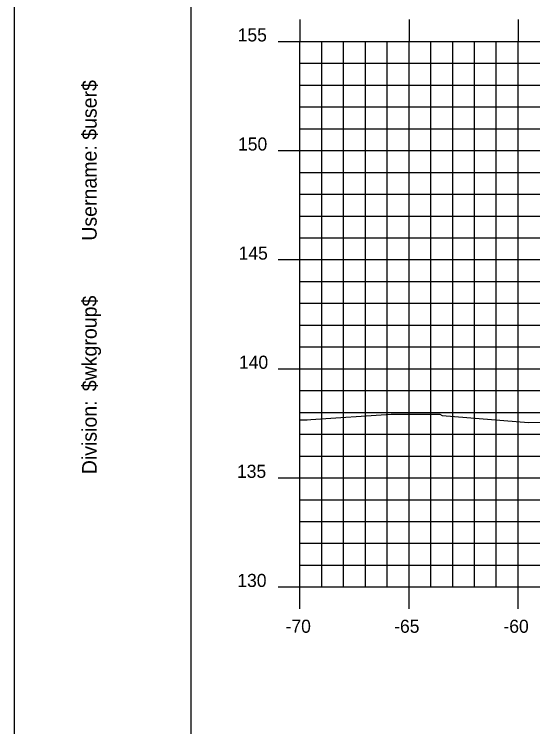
# Model space of a CAD drawing. Extents: x 851639 to 851810, y 365876 to 365986.
# Drawn here: x 851638.56 to 851662.32, y 365908.43 to 365941.08 of the extents above; entities that cross this region are included whole.
import ezdxf

# ---------------------------------------------------------------- set-up
doc = ezdxf.new("R2010")
doc.units = 0
for name, color, linetype in [('BORDER', 7, 'Continuous'), ('H_V ANNOTATION', 7, 'Continuous'), ('MAJOR', 7, 'Continuous'), ('MINOR', 7, 'Continuous'), ('PLOT BOUNDARY', 7, 'Continuous'), ('S_Roadway_Centerline', 7, 'Continuous')]:
    doc.layers.add(name, color=color, linetype=linetype)

msp = doc.modelspace()

# ---------------------------------------------------------------- linework, layer by layer
at = {"layer": 'BORDER'}
msp.add_lwpolyline([(851646.655, 365878.833), (851806.655, 365878.833), (851806.655, 365983.833), (851646.655, 365983.833)], close=True, dxfattribs=at)
at = {"layer": 'MAJOR'}
for p, q in [((851651.655, 365940.835), (851651.655, 365939.833)), ((851656.655, 365940.835), (851656.655, 365939.833)), ((851661.655, 365940.835), (851661.655, 365939.833)), ((851650.653, 365939.833), (851651.655, 365939.833)), ((851651.655, 365939.833), (851791.655, 365939.833)), ((851651.655, 365914.833), (851651.655, 365939.833)), ((851651.655, 365914.833), (851651.655, 365939.833)), ((851651.655, 365939.833), (851791.655, 365939.833)), ((851656.655, 365914.833), (851656.655, 365939.833)), ((851661.655, 365914.833), (851661.655, 365939.833)), ((851650.653, 365934.833), (851651.655, 365934.833)), ((851651.655, 365934.833), (851791.655, 365934.833)), ((851650.653, 365929.833), (851651.655, 365929.833)), ((851651.655, 365929.833), (851791.655, 365929.833)), ((851650.653, 365924.833), (851651.655, 365924.833)), ((851651.655, 365924.833), (851791.655, 365924.833)), ((851650.653, 365919.833), (851651.655, 365919.833)), ((851651.655, 365919.833), (851791.655, 365919.833)), ((851650.653, 365914.833), (851651.655, 365914.833)), ((851651.655, 365914.833), (851791.655, 365914.833)), ((851651.655, 365914.833), (851791.655, 365914.833)), ((851651.655, 365913.831), (851651.655, 365914.833)), ((851656.655, 365913.831), (851656.655, 365914.833)), ((851661.655, 365913.831), (851661.655, 365914.833))]:
    msp.add_line(p, q, dxfattribs=at)
at = {"layer": 'MINOR'}
for p, q in [((851652.655, 365914.833), (851652.655, 365939.833)), ((851653.655, 365914.833), (851653.655, 365939.833)), ((851654.655, 365914.833), (851654.655, 365939.833)), ((851655.655, 365914.833), (851655.655, 365939.833)), ((851657.655, 365914.833), (851657.655, 365939.833)), ((851658.655, 365914.833), (851658.655, 365939.833)), ((851659.655, 365914.833), (851659.655, 365939.833)), ((851660.655, 365914.833), (851660.655, 365939.833)), ((851651.655, 365938.833), (851791.655, 365938.833)), ((851651.655, 365938.833), (851652.657, 365938.833)), ((851651.655, 365937.833), (851791.655, 365937.833)), ((851651.655, 365937.833), (851652.657, 365937.833)), ((851651.655, 365936.833), (851791.655, 365936.833)), ((851651.655, 365936.833), (851652.657, 365936.833)), ((851651.655, 365935.833), (851791.655, 365935.833)), ((851651.655, 365935.833), (851652.657, 365935.833)), ((851651.655, 365933.833), (851791.655, 365933.833)), ((851651.655, 365933.833), (851652.657, 365933.833)), ((851651.655, 365932.833), (851791.655, 365932.833)), ((851651.655, 365932.833), (851652.657, 365932.833)), ((851651.655, 365931.833), (851791.655, 365931.833)), ((851651.655, 365931.833), (851652.657, 365931.833)), ((851651.655, 365930.833), (851791.655, 365930.833)), ((851651.655, 365930.833), (851652.657, 365930.833)), ((851651.655, 365928.833), (851791.655, 365928.833)), ((851651.655, 365928.833), (851652.657, 365928.833)), ((851651.655, 365927.833), (851791.655, 365927.833)), ((851651.655, 365927.833), (851652.657, 365927.833)), ((851651.655, 365926.833), (851791.655, 365926.833)), ((851651.655, 365926.833), (851652.657, 365926.833)), ((851651.655, 365925.833), (851791.655, 365925.833)), ((851651.655, 365925.833), (851652.657, 365925.833)), ((851651.655, 365923.833), (851791.655, 365923.833)), ((851651.655, 365923.833), (851652.657, 365923.833)), ((851651.655, 365922.833), (851791.655, 365922.833)), ((851651.655, 365922.833), (851652.657, 365922.833)), ((851651.655, 365921.833), (851791.655, 365921.833)), ((851651.655, 365921.833), (851652.657, 365921.833)), ((851651.655, 365920.833), (851791.655, 365920.833)), ((851651.655, 365920.833), (851652.657, 365920.833)), ((851651.655, 365918.833), (851791.655, 365918.833)), ((851651.655, 365918.833), (851652.657, 365918.833)), ((851651.655, 365917.833), (851791.655, 365917.833)), ((851651.655, 365917.833), (851652.657, 365917.833)), ((851651.655, 365916.833), (851791.655, 365916.833)), ((851651.655, 365916.833), (851652.657, 365916.833)), ((851651.655, 365915.833), (851791.655, 365915.833)), ((851651.655, 365915.833), (851652.657, 365915.833))]:
    msp.add_line(p, q, dxfattribs=at)
at = {"layer": 'PLOT BOUNDARY'}
msp.add_lwpolyline([(851638.562, 365875.774), (851808.562, 365875.774), (851808.562, 365985.774), (851638.562, 365985.774)], close=True, dxfattribs=at)
at = {"layer": 'S_Roadway_Centerline'}
msp.add_lwpolyline([(851651.655, 365922.491), (851651.949, 365922.492), (851651.993, 365922.485), (851652.16, 365922.501), (851655.843, 365922.751), (851658.065, 365922.756), (851658.171, 365922.691), (851662.127, 365922.37), (851663.756, 365922.395), (851664.788, 365922.378), (851664.934, 365922.24), (851667.544, 365922.499), (851674.034, 365922.745), (851678.105, 365922.897), (851685.154, 365922.948), (851686.808, 365923.06), (851686.992, 365923.011), (851693.639, 365923.14)], dxfattribs=at)

# ---------------------------------------------------------------- texts
at = {"layer": 'BORDER'}
for s, p in [('$user$', (851642.34, 365935.325)), ('Username:', (851642.34, 365930.701)), ('$wkgroup$', (851642.34, 365923.803)), ('Division:', (851642.34, 365919.999))]:
    msp.add_text(s, height=0.6696, rotation=90, dxfattribs=at).set_placement(p)
at = {"layer": 'H_V ANNOTATION'}
for s, p in [('155', (851648.801, 365939.833)), ('150', (851648.817, 365934.833)), ('145', (851648.844, 365929.833)), ('140', (851648.86, 365924.833)), ('135', (851648.769, 365919.833)), ('130', (851648.785, 365914.833)), ('-70', (851650.997, 365912.733)), ('-65', (851655.973, 365912.733)), ('-60', (851660.981, 365912.733))]:
    msp.add_text(s, height=0.6, dxfattribs=at).set_placement(p)
at = {"layer": 'MAJOR'}
msp.add_text('-', height=0.006, dxfattribs=at).set_placement((851651.65, 365914.833))

doc.saveas('drawing.dxf')
